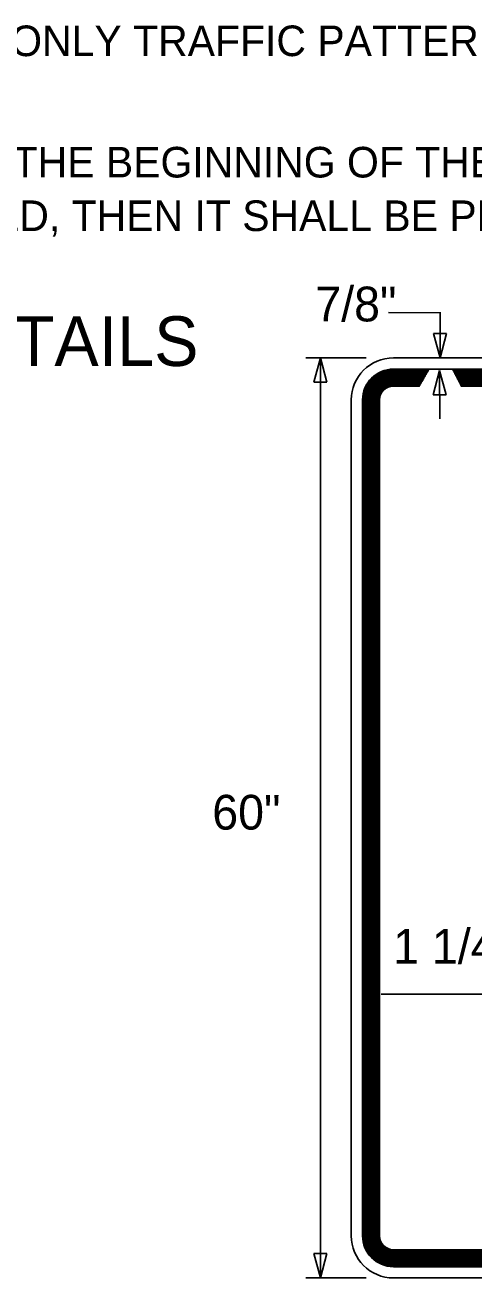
# Model space of a CAD drawing. Extents: x 15277 to 18126, y 1908 to 6555.
# Drawn here: x 17744.9 to 17853.3, y 2366.5 to 2669.2 of the extents above; entities that cross this region are included whole.
import ezdxf

# ---------------------------------------------------------------- set-up
doc = ezdxf.new("R2010")
doc.units = 0
doc.layers.add('TYPICAL_EX', color=7, linetype='Continuous')
doc.layers.add('TYPICAL_TEXT_DIMEN_PR', color=7, linetype='Continuous')

msp = doc.modelspace()

# ---------------------------------------------------------------- linework, layer by layer
at = {"layer": 'TYPICAL_EX'}
for p, q in [((17976.4, 2588.82), (17833.88, 2588.82)), ((17842.58, 2586.1), (17833.89, 2586.1)), ((17842.52, 2585.99), (17833.89, 2585.99)), ((17842.45, 2585.88), (17833.89, 2585.88)), ((17842.39, 2585.77), (17833.89, 2585.77)), ((17842.32, 2585.66), (17833.89, 2585.66)), ((17842.26, 2585.54), (17833.89, 2585.54)), ((17842.19, 2585.43), (17833.89, 2585.43)), ((17842.13, 2585.32), (17833.89, 2585.32)), ((17842.06, 2585.21), (17833.89, 2585.21)), ((17842, 2585.1), (17833.89, 2585.1)), ((17841.94, 2584.98), (17833.89, 2584.98)), ((17846.51, 2586.1), (17842.51, 2586.1)), ((17976.4, 2586.1), (17846.51, 2586.1)), ((17976.4, 2585.99), (17848.04, 2585.99)), ((17976.4, 2585.88), (17848.18, 2585.88)), ((17976.4, 2585.77), (17848.24, 2585.77)), ((17976.4, 2585.66), (17848.29, 2585.66)), ((17976.4, 2585.54), (17848.35, 2585.54)), ((17976.4, 2585.43), (17848.41, 2585.43)), ((17976.4, 2585.32), (17848.47, 2585.32)), ((17976.4, 2585.21), (17848.53, 2585.21)), ((17976.4, 2585.1), (17848.58, 2585.1)), ((17976.4, 2584.98), (17848.64, 2584.98)), ((17841.87, 2584.87), (17833.89, 2584.87)), ((17841.81, 2584.76), (17833.89, 2584.76)), ((17841.74, 2584.65), (17833.89, 2584.65)), ((17841.68, 2584.53), (17833.89, 2584.53)), ((17841.61, 2584.42), (17833.89, 2584.42)), ((17841.55, 2584.31), (17833.89, 2584.31)), ((17841.48, 2584.2), (17833.89, 2584.2)), ((17841.42, 2584.09), (17833.89, 2584.09)), ((17841.35, 2583.97), (17833.89, 2583.97)), ((17841.29, 2583.86), (17833.89, 2583.86)), ((17841.22, 2583.75), (17833.89, 2583.75)), ((17841.16, 2583.64), (17833.89, 2583.64)), ((17841.1, 2583.53), (17833.89, 2583.53)), ((17841.03, 2583.41), (17833.89, 2583.41)), ((17840.97, 2583.3), (17833.89, 2583.3)), ((17840.9, 2583.19), (17833.89, 2583.19)), ((17840.84, 2583.08), (17833.89, 2583.08)), ((17840.77, 2582.97), (17833.89, 2582.97)), ((17840.71, 2582.85), (17833.89, 2582.85)), ((17840.64, 2582.74), (17833.89, 2582.74)), ((17840.58, 2582.63), (17833.89, 2582.63)), ((17840.51, 2582.52), (17833.89, 2582.52)), ((17840.45, 2582.41), (17833.89, 2582.41)), ((17840.39, 2582.29), (17833.89, 2582.29)), ((17840.32, 2582.18), (17833.89, 2582.18)), ((17840.26, 2582.07), (17833.89, 2582.07)), ((17840.21, 2581.99), (17833.89, 2581.99)), ((17976.4, 2584.87), (17848.7, 2584.87)), ((17976.4, 2584.76), (17848.76, 2584.76)), ((17976.4, 2584.65), (17848.82, 2584.65)), ((17976.4, 2584.53), (17848.87, 2584.53)), ((17976.4, 2584.42), (17848.93, 2584.42)), ((17976.4, 2584.31), (17848.99, 2584.31)), ((17976.26, 2584.2), (17849.05, 2584.2)), ((17975.99, 2584.09), (17849.1, 2584.09)), ((17975.7, 2583.97), (17849.16, 2583.97)), ((17975.42, 2583.86), (17849.22, 2583.86)), ((17975.14, 2583.75), (17849.28, 2583.75)), ((17974.86, 2583.64), (17849.34, 2583.64)), ((17974.58, 2583.53), (17849.4, 2583.53)), ((17974.3, 2583.41), (17849.45, 2583.41)), ((17974.02, 2583.3), (17849.51, 2583.3)), ((17973.74, 2583.19), (17849.57, 2583.19)), ((17973.46, 2583.08), (17849.63, 2583.08)), ((17973.18, 2582.97), (17849.69, 2582.97)), ((17972.9, 2582.85), (17849.74, 2582.85)), ((17972.62, 2582.74), (17849.8, 2582.74)), ((17972.34, 2582.63), (17849.86, 2582.63)), ((17972.06, 2582.52), (17849.92, 2582.52)), ((17971.78, 2582.41), (17849.97, 2582.41)), ((17971.49, 2582.29), (17850.03, 2582.29)), ((17971.21, 2582.18), (17850.09, 2582.18)), ((17970.93, 2582.07), (17850.15, 2582.07)), ((17970.75, 2581.99), (17850.19, 2581.99)), ((17823.7, 2578.64), (17823.7, 2430.55)), ((17826.42, 2578.64), (17826.42, 2430.55)), ((17826.53, 2578.64), (17826.53, 2430.55)), ((17826.64, 2578.64), (17826.64, 2430.55)), ((17826.76, 2578.64), (17826.76, 2430.55)), ((17826.87, 2578.64), (17826.87, 2430.42)), ((17826.98, 2578.64), (17826.98, 2430.55)), ((17827.09, 2578.64), (17827.09, 2430.55)), ((17827.2, 2578.64), (17827.2, 2430.53)), ((17827.32, 2578.64), (17827.32, 2430.56)), ((17827.43, 2578.64), (17827.43, 2430.51)), ((17827.54, 2578.64), (17827.54, 2430.55)), ((17827.65, 2578.64), (17827.65, 2430.55)), ((17827.76, 2578.64), (17827.76, 2430.59)), ((17827.88, 2578.64), (17827.88, 2430.55)), ((17827.99, 2578.64), (17827.99, 2430.55)), ((17828.1, 2578.64), (17828.1, 2430.55)), ((17828.21, 2578.64), (17828.21, 2430.55)), ((17828.33, 2578.64), (17828.33, 2430.55)), ((17828.44, 2578.64), (17828.44, 2430.54)), ((17828.55, 2578.64), (17828.55, 2430.55)), ((17828.66, 2578.64), (17828.66, 2430.56)), ((17828.77, 2578.64), (17828.77, 2430.55)), ((17828.89, 2578.64), (17828.89, 2430.55)), ((17829, 2578.64), (17829, 2430.54)), ((17829.11, 2578.64), (17829.11, 2430.57)), ((17829.22, 2578.64), (17829.22, 2430.55)), ((17829.33, 2578.64), (17829.33, 2430.55)), ((17829.44, 2578.64), (17829.44, 2449.25)), ((17829.56, 2578.64), (17829.56, 2449.25)), ((17829.67, 2578.64), (17829.67, 2449.25)), ((17829.78, 2578.64), (17829.78, 2430.55)), ((17829.89, 2578.64), (17829.89, 2430.54)), ((17830.01, 2578.64), (17830.01, 2430.55)), ((17830.12, 2578.64), (17830.12, 2430.54)), ((17830.23, 2578.64), (17830.23, 2430.55)), ((17830.34, 2578.64), (17830.34, 2430.57)), ((17830.45, 2578.64), (17830.45, 2430.56)), ((17830.53, 2578.64), (17830.53, 2430.57)), ((17829.44, 2449.33), (17829.44, 2376.7)), ((17829.56, 2449.25), (17829.56, 2376.7)), ((17829.67, 2449.25), (17829.67, 2376.7)), ((17830.94, 2435.12), (17979.69, 2435.12)), ((17823.7, 2430.55), (17823.7, 2376.7)), ((17826.42, 2430.55), (17826.42, 2376.7)), ((17826.53, 2430.55), (17826.53, 2376.7)), ((17826.64, 2430.55), (17826.64, 2376.7)), ((17826.76, 2430.55), (17826.76, 2376.7)), ((17826.87, 2430.55), (17826.87, 2376.7)), ((17826.98, 2430.55), (17826.98, 2376.7)), ((17827.09, 2430.55), (17827.09, 2376.7)), ((17827.2, 2430.55), (17827.2, 2376.03)), ((17827.32, 2430.55), (17827.32, 2376.7)), ((17827.43, 2430.55), (17827.43, 2376.7)), ((17827.54, 2430.55), (17827.54, 2376.7)), ((17827.65, 2430.55), (17827.65, 2376.7)), ((17827.76, 2430.6), (17827.76, 2376.7)), ((17827.88, 2430.55), (17827.88, 2376.7)), ((17827.99, 2430.55), (17827.99, 2376.7)), ((17828.1, 2430.55), (17828.1, 2376.7)), ((17828.21, 2430.55), (17828.21, 2376.7)), ((17828.33, 2430.55), (17828.33, 2376.7)), ((17828.44, 2430.55), (17828.44, 2376.7)), ((17828.55, 2430.55), (17828.55, 2376.7)), ((17828.66, 2430.55), (17828.66, 2376.7)), ((17828.77, 2430.55), (17828.77, 2376.7)), ((17828.89, 2430.55), (17828.89, 2376.7)), ((17829, 2430.55), (17829, 2376.7)), ((17829.11, 2430.55), (17829.11, 2376.7)), ((17829.22, 2430.55), (17829.22, 2376.7)), ((17829.33, 2430.55), (17829.33, 2376.7)), ((17829.78, 2430.55), (17829.78, 2376.7)), ((17829.89, 2430.55), (17829.89, 2376.7)), ((17830.01, 2430.55), (17830.01, 2376.7)), ((17830.12, 2430.54), (17830.12, 2376.7)), ((17830.23, 2430.55), (17830.23, 2376.7)), ((17830.34, 2430.55), (17830.34, 2376.7)), ((17830.45, 2430.55), (17830.45, 2376.7)), ((17830.53, 2430.55), (17830.53, 2376.7)), ((17833.88, 2373.35), (17976.4, 2373.35)), ((17833.88, 2373.27), (17976.4, 2373.27)), ((17833.88, 2373.16), (17976.4, 2373.16)), ((17833.88, 2373.05), (17976.4, 2373.05)), ((17833.88, 2372.94), (17976.4, 2372.94)), ((17833.88, 2372.83), (17976.4, 2372.83)), ((17833.88, 2372.71), (17976.4, 2372.71)), ((17833.88, 2372.6), (17976.4, 2372.6)), ((17833.88, 2372.49), (17976.4, 2372.49)), ((17833.88, 2372.38), (17976.4, 2372.38)), ((17833.88, 2372.27), (17976.4, 2372.27)), ((17833.88, 2372.15), (17976.4, 2372.15)), ((17833.88, 2372.04), (17976.4, 2372.04)), ((17833.88, 2371.93), (17976.4, 2371.93)), ((17833.88, 2371.82), (17976.4, 2371.82)), ((17833.88, 2371.7), (17976.4, 2371.7)), ((17833.88, 2371.59), (17976.4, 2371.59)), ((17833.88, 2371.48), (17976.4, 2371.48)), ((17833.88, 2371.37), (17976.4, 2371.37)), ((17833.88, 2371.26), (17976.4, 2371.26)), ((17833.88, 2371.14), (17976.4, 2371.14)), ((17833.88, 2371.03), (17976.4, 2371.03)), ((17833.88, 2370.92), (17976.4, 2370.92)), ((17833.88, 2370.81), (17976.4, 2370.81)), ((17833.88, 2370.7), (17976.4, 2370.7)), ((17833.88, 2370.59), (17976.4, 2370.59)), ((17833.88, 2370.47), (17976.4, 2370.47)), ((17833.88, 2370.36), (17976.4, 2370.36)), ((17833.88, 2370.25), (17976.4, 2370.25)), ((17833.88, 2370.14), (17976.4, 2370.14)), ((17833.88, 2370.02), (17976.4, 2370.02)), ((17833.88, 2369.91), (17976.4, 2369.91)), ((17833.88, 2369.8), (17976.4, 2369.8)), ((17833.88, 2369.69), (17976.4, 2369.69)), ((17833.88, 2369.58), (17976.4, 2369.58)), ((17833.88, 2369.46), (17976.4, 2369.46)), ((17833.88, 2369.35), (17976.4, 2369.35)), ((17833.88, 2369.24), (17976.4, 2369.24)), ((17833.88, 2366.53), (17976.4, 2366.53))]:
    msp.add_line(p, q, dxfattribs=at)
for centre, radius, start, end in [((17833.88, 2578.64), 10.18, 90, 180), ((17833.88, 2578.64), 7.46, 90, 180), ((17833.88, 2578.64), 7.35, 90, 180), ((17833.88, 2578.64), 7.24, 90, 180), ((17833.88, 2578.64), 7.13, 90, 180), ((17833.88, 2578.64), 7.02, 90, 180), ((17833.88, 2578.64), 6.9, 90, 180), ((17833.88, 2578.64), 6.79, 90, 180), ((17833.88, 2578.64), 6.68, 90, 180), ((17833.88, 2578.64), 6.57, 90, 180), ((17833.88, 2578.64), 6.46, 90, 180), ((17833.88, 2578.64), 6.34, 90, 180), ((17833.88, 2578.64), 6.23, 90, 180), ((17833.88, 2578.64), 6.12, 90, 180), ((17833.88, 2578.64), 6.01, 90, 180), ((17833.88, 2578.64), 5.9, 90, 180), ((17833.88, 2578.64), 5.78, 90, 180), ((17833.88, 2578.64), 5.67, 90, 180), ((17833.88, 2578.64), 5.56, 90, 180), ((17833.88, 2578.64), 5.45, 90, 180), ((17833.88, 2578.64), 5.34, 90, 180), ((17833.88, 2578.64), 5.22, 90, 180), ((17833.88, 2578.64), 5.11, 90, 180), ((17833.88, 2578.64), 5, 90, 180), ((17833.88, 2578.64), 4.89, 90, 180), ((17833.88, 2578.64), 4.78, 90, 180), ((17833.88, 2578.64), 4.66, 90, 180), ((17833.88, 2578.64), 4.55, 90, 180), ((17833.88, 2578.64), 4.44, 90, 180), ((17833.88, 2578.64), 4.33, 90, 180), ((17833.88, 2578.64), 4.21, 90, 180), ((17833.88, 2578.64), 4.1, 90, 180), ((17833.88, 2578.64), 3.99, 90, 180), ((17833.88, 2578.64), 3.88, 90, 180), ((17833.88, 2578.64), 3.77, 90, 180), ((17833.88, 2578.64), 3.65, 90, 180), ((17833.88, 2578.64), 3.54, 90, 180), ((17833.88, 2578.64), 3.43, 90, 180), ((17833.88, 2578.64), 3.36, 90, 180), ((17833.88, 2376.71), 10.18, 180, 270), ((17833.88, 2376.71), 7.46, 180, 270), ((17833.88, 2376.71), 7.35, 180, 270), ((17833.88, 2376.71), 7.24, 180, 270), ((17833.88, 2376.71), 7.13, 180, 270), ((17833.88, 2376.71), 7.02, 180, 270), ((17833.88, 2376.71), 6.9, 180, 270), ((17833.88, 2376.71), 6.79, 180, 270), ((17833.88, 2376.71), 6.68, 180, 270), ((17833.88, 2376.71), 6.57, 180, 270), ((17833.88, 2376.71), 6.46, 180, 270), ((17833.88, 2376.71), 6.34, 180, 270), ((17833.88, 2376.71), 6.23, 180, 270), ((17833.88, 2376.71), 6.12, 180, 270), ((17833.88, 2376.71), 6.01, 180, 270), ((17833.88, 2376.71), 5.9, 180, 270), ((17833.88, 2376.71), 5.78, 180, 270), ((17833.88, 2376.71), 5.67, 180, 270), ((17833.88, 2376.71), 5.56, 180, 270), ((17833.88, 2376.71), 5.45, 180, 270), ((17833.88, 2376.71), 5.34, 180, 270), ((17833.88, 2376.71), 5.22, 180, 270), ((17833.88, 2376.71), 5.11, 180, 270), ((17833.88, 2376.71), 5, 180, 270), ((17833.88, 2376.71), 4.89, 180, 270), ((17833.88, 2376.71), 4.78, 180, 270), ((17833.88, 2376.71), 4.66, 180, 270), ((17833.88, 2376.71), 4.55, 180, 270), ((17833.88, 2376.71), 4.44, 180, 270), ((17833.88, 2376.71), 4.33, 180, 270), ((17833.88, 2376.71), 4.21, 180, 270), ((17833.88, 2376.71), 4.1, 180, 270), ((17833.88, 2376.71), 3.99, 180, 270), ((17833.88, 2376.71), 3.88, 180, 270), ((17833.88, 2376.71), 3.77, 180, 270), ((17833.88, 2376.71), 3.65, 180, 270), ((17833.88, 2376.71), 3.54, 180, 270), ((17833.88, 2376.71), 3.43, 180, 270), ((17833.88, 2376.71), 3.36, 180, 270)]:
    msp.add_arc(centre, radius, start, end, dxfattribs=at)
at = {"layer": 'TYPICAL_TEXT_DIMEN_PR'}
for p, q in [((17832.69, 2599.74), (17845.14, 2599.72)), ((17845.14, 2588.82), (17845.13, 2599.82)), ((17845.14, 2588.82), (17843.57, 2594.68)), ((17843.57, 2594.68), (17845.14, 2594.68)), ((17845.14, 2594.68), (17846.71, 2594.68)), ((17846.71, 2594.68), (17845.14, 2588.82)), ((17827.33, 2588.82), (17812.72, 2588.82)), ((17814.69, 2582.96), (17816.26, 2588.82)), ((17816.26, 2430.55), (17816.26, 2588.82)), ((17816.26, 2588.82), (17817.83, 2582.96)), ((17843.48, 2579.91), (17845.03, 2585.77)), ((17845.06, 2574.06), (17845.03, 2585.77)), ((17845.03, 2585.77), (17846.62, 2579.91)), ((17816.26, 2582.96), (17814.69, 2582.96)), ((17817.83, 2582.96), (17816.26, 2582.96)), ((17845.05, 2579.91), (17843.48, 2579.91)), ((17846.62, 2579.91), (17845.05, 2579.91)), ((17816.26, 2366.53), (17816.26, 2430.55)), ((17816.26, 2366.53), (17814.69, 2372.39)), ((17814.69, 2372.39), (17816.26, 2372.39)), ((17816.26, 2372.39), (17817.83, 2372.39)), ((17817.83, 2372.39), (17816.26, 2366.53)), ((17827.33, 2366.53), (17812.72, 2366.53))]:
    msp.add_line(p, q, dxfattribs=at)

# ---------------------------------------------------------------- texts
for s, height, p in [('PATTERN.  EXCEPTION WILL BE MADE FOR DAYTIME-ONLY TRAFFIC PATTERNS THAT ARE ADEQUATELY DELINEATED BY', 7.392, (17483.23, 2661.71)), ('THE LIGHTED ARROW PANEL SHALL BE LOCATED AT THE BEGINNING OF THE TAPER AS SHOWN.  WHEN PHYSICAL', 7.392, (17483.23, 2632.39)), ('LIMITATIONS RESTRICT ITS PLACEMENT AS INDICATED, THEN IT SHALL BE PLACED AS CLOSE TO THE BEGINNING', 7.392, (17483.23, 2619.45)), ('7/8"', 8.4, (17815.02, 2597.62)), ('SIGN DETAILS', 12, (17676.24, 2586.85)), ('60"', 8.4, (17790.14, 2474.84)), ('1 1/4"', 8.4, (17833.8, 2442.45))]:
    msp.add_text(s, height=height, dxfattribs=at).set_placement(p)

doc.saveas('drawing.dxf')
